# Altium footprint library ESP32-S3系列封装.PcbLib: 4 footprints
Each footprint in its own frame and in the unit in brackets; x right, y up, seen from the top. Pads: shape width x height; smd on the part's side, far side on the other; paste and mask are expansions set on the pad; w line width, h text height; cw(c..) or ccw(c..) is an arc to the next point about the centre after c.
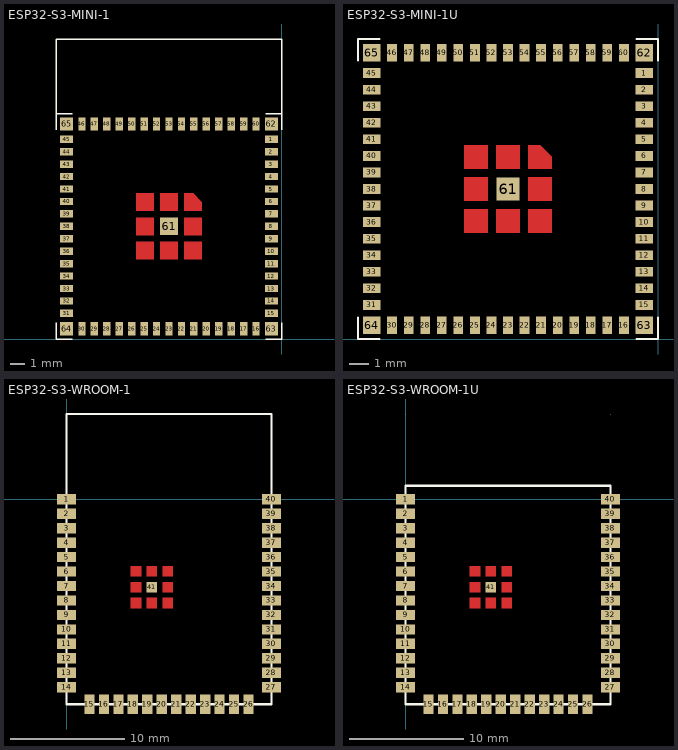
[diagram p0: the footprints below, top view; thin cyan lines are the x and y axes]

## ESP32-S3-MINI-1 [mm]
height 0.61
pads (65):
  rect 0.9x0.5 smd paste-0.05 mask-0.05: 1(-0.7,13.65) 2(-0.7,12.8) 3(-0.7,11.95) 4(-0.7,11.1) 5(-0.7,10.25) 6(-0.7,9.4) 7(-0.7,8.55) 8(-0.7,7.7) 9(-0.7,6.85) 10(-0.7,6) 11(-0.7,5.15) 12(-0.7,4.3) 13(-0.7,3.45) 14(-0.7,2.6) 15(-0.7,1.75) 31(-14.7,1.75) 32(-14.7,2.6) 33(-14.7,3.45) 34(-14.7,4.3) 35(-14.7,5.15) 36(-14.7,6) 37(-14.7,6.85) 38(-14.7,7.7) 39(-14.7,8.55) 40(-14.7,9.4) 41(-14.7,10.25) 42(-14.7,11.1) 43(-14.7,11.95) 44(-14.7,12.8) 45(-14.7,13.65)
  rect 0.5x0.9 smd paste-0.05 mask-0.05: 16(-1.75,0.7) 17(-2.6,0.7) 18(-3.45,0.7) 19(-4.3,0.7) 20(-5.15,0.7) 21(-6,0.7) 22(-6.85,0.7) 23(-7.7,0.7) 24(-8.55,0.7) 25(-9.4,0.7) 26(-10.25,0.7) 27(-11.1,0.7) 28(-11.95,0.7) 29(-12.8,0.7) 30(-13.65,0.7) 46(-13.65,14.7) 47(-12.8,14.7) 48(-11.95,14.7) 49(-11.1,14.7) 50(-10.25,14.7) 51(-9.4,14.7) 52(-8.55,14.7) 53(-7.7,14.7) 54(-6.85,14.7) 55(-6,14.7) 56(-5.15,14.7) 57(-4.3,14.7) 58(-3.45,14.7) 59(-2.6,14.7) 60(-1.75,14.7)
  rect 1.2x1.2 smd: 61(-7.7,7.7)
  rect 0.9x0.9 smd paste-0.05 mask-0.05: 62(-0.7,14.7) 63(-0.7,0.7) 64(-14.7,0.7) 65(-14.7,14.7)
Top Layer:
  region: -8.3,9.95 -7.1,9.95 -7.1,8.75 -8.3,8.75
  region: -9.95,9.95 -8.75,9.95 -8.75,8.75 -9.95,8.75
  region: -9.95,8.3 -8.75,8.3 -8.75,7.1 -9.95,7.1
  region: -9.95,6.65 -8.75,6.65 -8.75,5.45 -9.95,5.45
  region: -8.3,6.65 -7.1,6.65 -7.1,5.45 -8.3,5.45
  region: -6.65,6.65 -5.45,6.65 -5.45,5.45 -6.65,5.45
  region: -6.65,8.3 -5.45,8.3 -5.45,7.1 -6.65,7.1
  region: -6.65,9.95 -6.05,9.95 -5.45,9.35 -5.45,8.75 -6.65,8.75
Top Overlay:
  lines w0.102: -15.4,1.1 -15.4,0 -14.3,0 ; -15.4,14.3 -15.4,15.4 -14.3,15.4 ; -15.4,14.9 -15.4,20.5 0,20.5 0,14.9 ; -1.1,0 0,0 0,1.1 ; -1.1,15.4 0,15.4 0,14.3
Top Paste:
  region: -9.95,6.65 -8.75,6.65 -8.75,5.45 -9.95,5.45
  region: -8.3,6.65 -7.1,6.65 -7.1,5.45 -8.3,5.45
  region: -6.65,6.65 -5.45,6.65 -5.45,5.45 -6.65,5.45
  region: -6.65,8.3 -5.45,8.3 -5.45,7.1 -6.65,7.1
  region: -6.65,9.95 -6.05,9.95 -5.45,9.35 -5.45,8.75 -6.65,8.75
  region: -9.95,8.3 -8.75,8.3 -8.75,7.1 -9.95,7.1
  region: -9.95,9.95 -8.75,9.95 -8.75,8.75 -9.95,8.75
  region: -8.3,9.95 -7.1,9.95 -7.1,8.75 -8.3,8.75
Top Solder:
  region: -6.65,9.95 -6.05,9.95 -5.45,9.35 -5.45,8.75 -6.65,8.75
  region: -6.65,8.3 -5.45,8.3 -5.45,7.1 -6.65,7.1
  region: -6.65,6.65 -5.45,6.65 -5.45,5.45 -6.65,5.45
  region: -8.3,6.65 -7.1,6.65 -7.1,5.45 -8.3,5.45
  region: -9.95,6.65 -8.75,6.65 -8.75,5.45 -9.95,5.45
  region: -9.95,8.3 -8.75,8.3 -8.75,7.1 -9.95,7.1
  region: -9.95,9.95 -8.75,9.95 -8.75,8.75 -9.95,8.75
  region: -8.3,9.95 -7.1,9.95 -7.1,8.75 -8.3,8.75

## ESP32-S3-MINI-1U [mm]
pads (65):
  rect 0.9x0.5 smd paste-0.05 mask-0.05: 1(-0.7,13.65) 2(-0.7,12.8) 3(-0.7,11.95) 4(-0.7,11.1) 5(-0.7,10.25) 6(-0.7,9.4) 7(-0.7,8.55) 8(-0.7,7.7) 9(-0.7,6.85) 10(-0.7,6) 11(-0.7,5.15) 12(-0.7,4.3) 13(-0.7,3.45) 14(-0.7,2.6) 15(-0.7,1.75) 31(-14.7,1.75) 32(-14.7,2.6) 33(-14.7,3.45) 34(-14.7,4.3) 35(-14.7,5.15) 36(-14.7,6) 37(-14.7,6.85) 38(-14.7,7.7) 39(-14.7,8.55) 40(-14.7,9.4) 41(-14.7,10.25) 42(-14.7,11.1) 43(-14.7,11.95) 44(-14.7,12.8) 45(-14.7,13.65)
  rect 0.5x0.9 smd paste-0.05 mask-0.05: 16(-1.75,0.7) 17(-2.6,0.7) 18(-3.45,0.7) 19(-4.3,0.7) 20(-5.15,0.7) 21(-6,0.7) 22(-6.85,0.7) 23(-7.7,0.7) 24(-8.55,0.7) 25(-9.4,0.7) 26(-10.25,0.7) 27(-11.1,0.7) 28(-11.95,0.7) 29(-12.8,0.7) 30(-13.65,0.7) 46(-13.65,14.7) 47(-12.8,14.7) 48(-11.95,14.7) 49(-11.1,14.7) 50(-10.25,14.7) 51(-9.4,14.7) 52(-8.55,14.7) 53(-7.7,14.7) 54(-6.85,14.7) 55(-6,14.7) 56(-5.15,14.7) 57(-4.3,14.7) 58(-3.45,14.7) 59(-2.6,14.7) 60(-1.75,14.7)
  rect 1.2x1.2 smd: 61(-7.7,7.7)
  rect 0.9x0.9 smd paste-0.05 mask-0.05: 62(-0.7,14.7) 63(-0.7,0.7) 64(-14.7,0.7) 65(-14.7,14.7)
Top Layer:
  region: -8.3,9.95 -7.1,9.95 -7.1,8.75 -8.3,8.75
  region: -9.95,9.95 -8.75,9.95 -8.75,8.75 -9.95,8.75
  region: -9.95,8.3 -8.75,8.3 -8.75,7.1 -9.95,7.1
  region: -9.95,6.65 -8.75,6.65 -8.75,5.45 -9.95,5.45
  region: -8.3,6.65 -7.1,6.65 -7.1,5.45 -8.3,5.45
  region: -6.65,6.65 -5.45,6.65 -5.45,5.45 -6.65,5.45
  region: -6.65,8.3 -5.45,8.3 -5.45,7.1 -6.65,7.1
  region: -6.65,9.95 -6.05,9.95 -5.45,9.35 -5.45,8.75 -6.65,8.75
Top Overlay:
  lines w0.102: -15.4,1.1 -15.4,0 -14.3,0 ; -15.4,14.3 -15.4,15.4 -14.3,15.4 ; -1.1,0 0,0 0,1.1 ; -1.1,15.4 0,15.4 0,14.3
Top Paste:
  region: -9.95,6.65 -8.75,6.65 -8.75,5.45 -9.95,5.45
  region: -8.3,6.65 -7.1,6.65 -7.1,5.45 -8.3,5.45
  region: -6.65,6.65 -5.45,6.65 -5.45,5.45 -6.65,5.45
  region: -6.65,8.3 -5.45,8.3 -5.45,7.1 -6.65,7.1
  region: -6.65,9.95 -6.05,9.95 -5.45,9.35 -5.45,8.75 -6.65,8.75
  region: -9.95,8.3 -8.75,8.3 -8.75,7.1 -9.95,7.1
  region: -9.95,9.95 -8.75,9.95 -8.75,8.75 -9.95,8.75
  region: -8.3,9.95 -7.1,9.95 -7.1,8.75 -8.3,8.75
Top Solder:
  region: -6.65,9.95 -6.05,9.95 -5.45,9.35 -5.45,8.75 -6.65,8.75
  region: -6.65,8.3 -5.45,8.3 -5.45,7.1 -6.65,7.1
  region: -6.65,6.65 -5.45,6.65 -5.45,5.45 -6.65,5.45
  region: -8.3,6.65 -7.1,6.65 -7.1,5.45 -8.3,5.45
  region: -9.95,6.65 -8.75,6.65 -8.75,5.45 -9.95,5.45
  region: -9.95,8.3 -8.75,8.3 -8.75,7.1 -9.95,7.1
  region: -9.95,9.95 -8.75,9.95 -8.75,8.75 -9.95,8.75
  region: -8.3,9.95 -7.1,9.95 -7.1,8.75 -8.3,8.75

## ESP32-S3-WROOM-1 [mm]
pads (41):
  rect 1.7x0.9 smd: 1(0,0) 2(0,-1.27) 3(0,-2.54) 4(0,-3.81) 5(0,-5.08) 6(0,-6.35) 7(0,-7.62) 8(0,-8.89) 9(0,-10.16) 10(0,-11.43) 11(0,-12.7) 12(0,-13.97) 13(0,-15.24) 14(0,-16.51) 27(18,-16.51) 28(18,-15.24) 29(18,-13.97) 30(18,-12.7) 31(18,-11.43) 32(18,-10.16) 33(18,-8.89) 34(18,-7.62) 35(18,-6.35) 36(18,-5.08) 37(18,-3.81) 38(18,-2.54) 39(18,-1.27) 40(18,0)
  rect 0.9x1.7 smd: 15(2.015,-18.01) 16(3.285,-18.01) 17(4.555,-18.01) 18(5.825,-18.01) 19(7.095,-18.01) 20(8.365,-18.01) 21(9.635,-18.01) 22(10.905,-18.01) 23(12.175,-18.01) 24(13.445,-18.01) 25(14.715,-18.01) 26(15.985,-18.01)
  rect 0.9x0.9 smd mask+0.102: 41(7.495,-7.719)
Top Layer:
  region: 5.645,-8.663 6.545,-8.663 6.545,-9.563 5.645,-9.563
  region: 7.042,-8.663 7.942,-8.663 7.942,-9.563 7.042,-9.563
  region: 8.439,-8.663 9.339,-8.663 9.339,-9.563 8.439,-9.563
  region: 8.439,-7.266 9.339,-7.266 9.339,-8.166 8.439,-8.166
  region: 8.439,-5.869 9.339,-5.869 9.339,-6.769 8.439,-6.769
  region: 7.042,-5.869 7.942,-5.869 7.942,-6.769 7.042,-6.769
  region: 5.645,-7.269 6.545,-7.269 6.545,-8.169 5.645,-8.169
  region: 5.645,-5.869 6.545,-5.869 6.545,-6.769 5.645,-6.769
Top Overlay:
  lines w0.025: 0,-1.27 0.001,-1.27 ; 0,0 0.001,0 ; 0,7.49 0.001,7.49 ; 18,-18.01 18.001,-18.01 ; 18,7.49 18.001,7.49 18,7.49
  lines w0.2: 0,-18.01 0,7.49 18,7.49 18,-18.01 0,-18.01
Top Solder:
  region: 8.439,-8.663 9.339,-8.663 9.339,-9.563 8.439,-9.563
  region: 7.042,-8.663 7.942,-8.663 7.942,-9.563 7.042,-9.563
  region: 5.645,-8.663 6.545,-8.663 6.545,-9.563 5.645,-9.563
  region: 5.645,-7.269 6.545,-7.269 6.545,-8.169 5.645,-8.169
  region: 5.645,-5.869 6.545,-5.869 6.545,-6.769 5.645,-6.769
  region: 7.042,-5.869 7.942,-5.869 7.942,-6.769 7.042,-6.769
  region: 8.439,-5.869 9.339,-5.869 9.339,-6.769 8.439,-6.769
  region: 8.439,-7.266 9.339,-7.266 9.339,-8.166 8.439,-8.166
  region: 5.645,-7.269 6.545,-7.269 6.545,-8.169 5.645,-8.169
  region: 5.645,-5.869 6.545,-5.869 6.545,-6.769 5.645,-6.769
  region: 7.042,-5.869 7.942,-5.869 7.942,-6.769 7.042,-6.769
  region: 8.439,-5.869 9.339,-5.869 9.339,-6.769 8.439,-6.769
  region: 8.439,-7.266 9.339,-7.266 9.339,-8.166 8.439,-8.166
  region: 5.645,-8.663 6.545,-8.663 6.545,-9.563 5.645,-9.563
  region: 7.042,-8.663 7.942,-8.663 7.942,-9.563 7.042,-9.563
  region: 8.439,-8.663 9.339,-8.663 9.339,-9.563 8.439,-9.563

## ESP32-S3-WROOM-1U [mm]
pads (41):
  rect 1.7x0.9 smd: 1(-0.001,0) 2(-0.001,-1.27) 3(-0.001,-2.54) 4(-0.001,-3.81) 5(-0.001,-5.08) 6(-0.001,-6.35) 7(-0.001,-7.62) 8(-0.001,-8.89) 9(-0.001,-10.16) 10(-0.001,-11.43) 11(-0.001,-12.7) 12(-0.001,-13.97) 13(-0.001,-15.24) 14(-0.001,-16.51) 27(17.999,-16.51) 28(17.999,-15.24) 29(17.999,-13.97) 30(17.999,-12.7) 31(17.999,-11.43) 32(17.999,-10.16) 33(17.999,-8.89) 34(17.999,-7.62) 35(17.999,-6.35) 36(17.999,-5.08) 37(17.999,-3.81) 38(17.999,-2.54) 39(17.999,-1.27) 40(17.999,0)
  rect 0.9x1.7 smd: 15(2.014,-18.01) 16(3.284,-18.01) 17(4.554,-18.01) 18(5.824,-18.01) 19(7.094,-18.01) 20(8.364,-18.01) 21(9.634,-18.01) 22(10.904,-18.01) 23(12.174,-18.01) 24(13.444,-18.01) 25(14.714,-18.01) 26(15.984,-18.01)
  rect 0.9x0.9 smd mask+0.102: 41(7.494,-7.719)
Top Layer:
  region: 5.644,-5.869 6.544,-5.869 6.544,-6.769 5.644,-6.769
  region: 5.644,-7.269 6.544,-7.269 6.544,-8.169 5.644,-8.169
  region: 7.041,-5.869 7.941,-5.869 7.941,-6.769 7.041,-6.769
  region: 8.438,-5.869 9.338,-5.869 9.338,-6.769 8.438,-6.769
  region: 8.438,-7.266 9.338,-7.266 9.338,-8.166 8.438,-8.166
  region: 8.438,-8.663 9.338,-8.663 9.338,-9.563 8.438,-9.563
  region: 7.041,-8.663 7.941,-8.663 7.941,-9.563 7.041,-9.563
  region: 5.644,-8.663 6.544,-8.663 6.544,-9.563 5.644,-9.563
Top Overlay:
  lines w0.025: -0.001,-1.27 0,-1.27 ; -0.001,0 0,0 ; -0.001,7.49 0,7.49 ; 17.999,7.49 18,7.49 ; 17.999,7.49 18,7.49 ; 17.999,-18.01 18,-18.01
  lines w0.2: -0.001,-18.01 17.999,-18.01 17.999,1.19 -0.001,1.19 -0.001,-18.01
Top Solder:
  region: 8.438,-8.663 9.338,-8.663 9.338,-9.563 8.438,-9.563
  region: 7.041,-8.663 7.941,-8.663 7.941,-9.563 7.041,-9.563
  region: 5.644,-8.663 6.544,-8.663 6.544,-9.563 5.644,-9.563
  region: 8.438,-7.266 9.338,-7.266 9.338,-8.166 8.438,-8.166
  region: 8.438,-5.869 9.338,-5.869 9.338,-6.769 8.438,-6.769
  region: 7.041,-5.869 7.941,-5.869 7.941,-6.769 7.041,-6.769
  region: 5.644,-5.869 6.544,-5.869 6.544,-6.769 5.644,-6.769
  region: 5.644,-7.269 6.544,-7.269 6.544,-8.169 5.644,-8.169
  region: 8.438,-7.266 9.338,-7.266 9.338,-8.166 8.438,-8.166
  region: 8.438,-5.869 9.338,-5.869 9.338,-6.769 8.438,-6.769
  region: 7.041,-5.869 7.941,-5.869 7.941,-6.769 7.041,-6.769
  region: 5.644,-5.869 6.544,-5.869 6.544,-6.769 5.644,-6.769
  region: 5.644,-7.269 6.544,-7.269 6.544,-8.169 5.644,-8.169
  region: 5.644,-8.663 6.544,-8.663 6.544,-9.563 5.644,-9.563
  region: 7.041,-8.663 7.941,-8.663 7.941,-9.563 7.041,-9.563
  region: 8.438,-8.663 9.338,-8.663 9.338,-9.563 8.438,-9.563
